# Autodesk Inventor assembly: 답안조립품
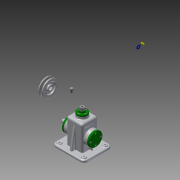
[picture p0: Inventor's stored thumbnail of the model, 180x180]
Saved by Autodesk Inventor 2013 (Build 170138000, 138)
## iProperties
Created: 2016-01
Part Number: 답안조립품
Document SubType Name: Assembly
Designer: Administrator
Author: Administrator
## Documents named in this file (19)
- C:\Users\Administrator\Desktop\460127V1006\답안조립품.iam
- C:\Users\Administrator\Desktop\460127V1006\1.본체.ipt
- C:\Users\Administrator\Desktop\460127V1006\V-벨트풀리.ipt
- C:\Users\Administrator\Desktop\460127V1006\고정핀.ipt
- C:\Users\Administrator\Desktop\460127V1006\뒤커버.ipt
- C:\Users\Administrator\Desktop\460127V1006\링크.ipt
- C:\Users\Administrator\Desktop\460127V1006\멈춤링 6 x 5.ipt
- C:\Users\Administrator\Desktop\460127V1006\멈춤링 15 x 1.ipt
- C:\Users\Administrator\Desktop\460127V1006\베어링 15 x 35 x 11.ipt
- C:\Users\Administrator\Desktop\460127V1006\볼트 M3 x 8.ipt
- C:\Users\Administrator\Desktop\460127V1006\볼트 M4 x 10.ipt
- C:\Users\Administrator\Desktop\460127V1006\볼트 M6 x 12.ipt
- C:\Users\Administrator\Desktop\460127V1006\상부부시.ipt
- C:\Users\Administrator\Desktop\460127V1006\슬라이드바.ipt
- C:\Users\Administrator\Desktop\460127V1006\앞커버.ipt
- C:\Users\Administrator\Desktop\460127V1006\오일실 15 25 7.ipt
- C:\Users\Administrator\Desktop\460127V1006\와셔.ipt
- C:\Users\Administrator\Desktop\460127V1006\키 5 x 5 x 14.ipt
- C:\Users\Administrator\Desktop\460127V1006\편심축.ipt
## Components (16 placed, 6 different names)
1. 1.본체:1
2. V-벨트풀리:1
3. 고정핀:1
4. ISO 4018 M6 x 12:1
5. ISO 4762 M4 x 10:1
6. ISO 4762 M4 x 10:2
7. ISO 4762 M4 x 10:3
8. ISO 4762 M4 x 10:4
9. ISO 4762 M4 x 10:5
10. ISO 4762 M4 x 10:6
11. ISO 4762 M4 x 10:7
12. ISO 4762 M4 x 10:8
13. ISO 4762 M3 x 8:1
14. ISO 4762 M3 x 8:2
15. ISO 4762 M3 x 8:3
16. ISO 4762 M3 x 8:4
